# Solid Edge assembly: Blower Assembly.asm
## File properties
Author: CADCIM
Template: NORMENG.ASM
Last saved by: MYPC
Revision: 7
Application: Solid Edge
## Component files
Lower Housing.par
upper housing.par
Blower.par
cover.par
motorshaft.par
Motor.par
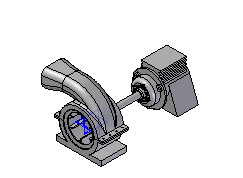
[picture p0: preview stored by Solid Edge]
